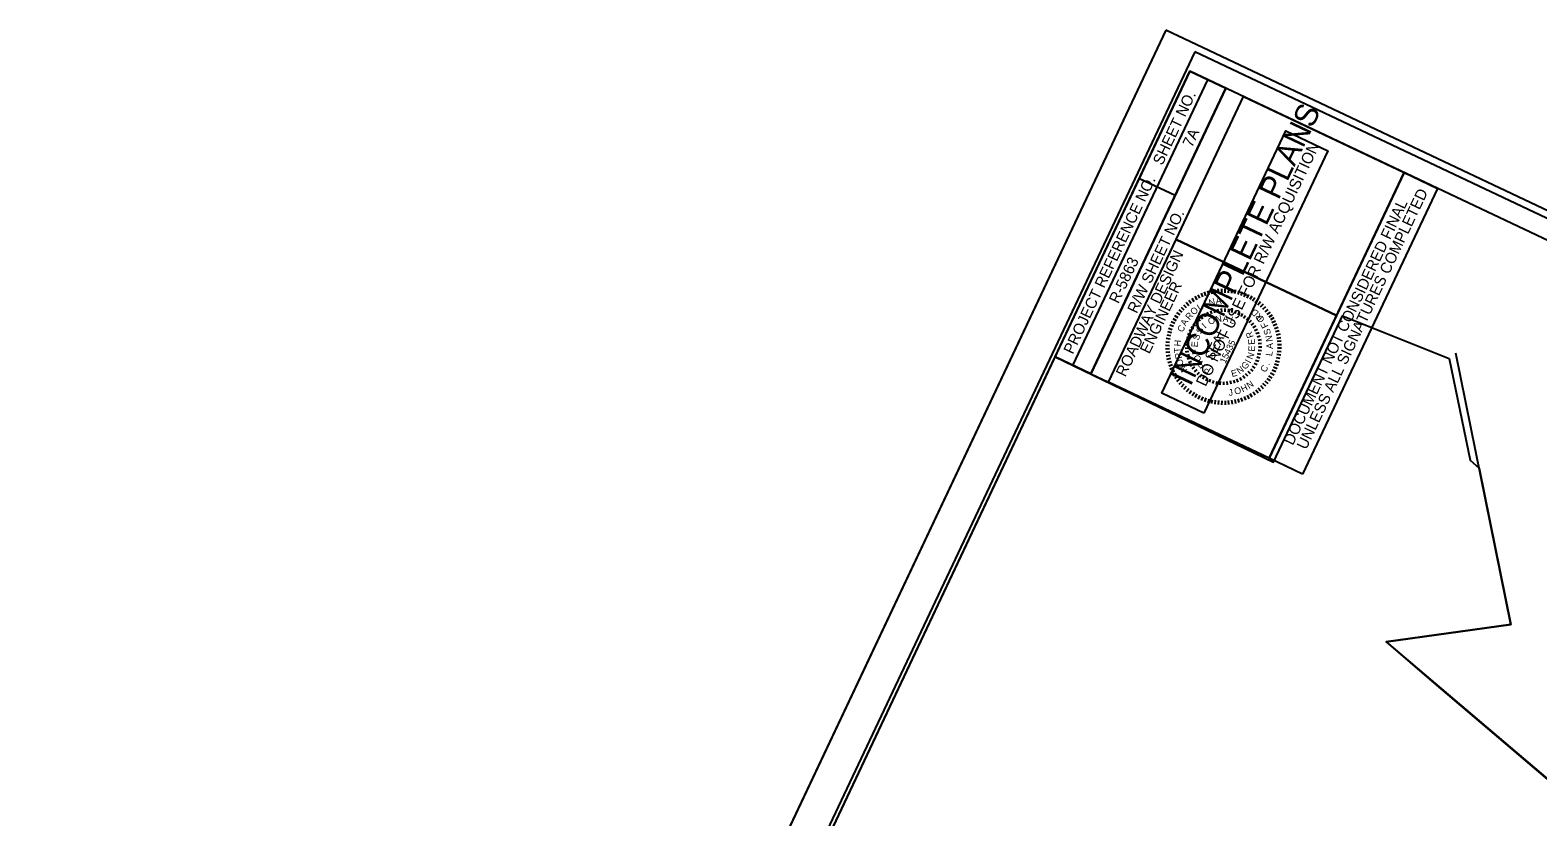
# Model space of a CAD drawing. Extents: x 556536 to 558250, y 505355 to 507347.
# Drawn here: x 556536 to 557491, y 506849 to 507347 of the extents above; entities that cross this region are included whole.
import ezdxf

# ---------------------------------------------------------------- set-up
doc = ezdxf.new("R2010")
doc.units = 0
for name, color, linetype in [('Matchline', 7, 'Continuous'), ('Old_Level_21', 7, 'Continuous'), ('Prop Horizontal Alignment Direction Label', 7, 'Continuous'), ('Prop SS Cut Line', 7, 'Continuous'), ('Prop SS Fill Line', 7, 'Continuous'), ('Prop SS Transition Line', 7, 'Continuous'), ('Scratch_Level_9', 7, 'Continuous'), ('Sheet Clip Boundary CELL', 7, 'Continuous'), ('Sheet Sticker Exception Certification CELL', 7, 'Continuous'), ('Sheet Sticker Incomplete CELL', 7, 'Continuous')]:
    doc.layers.add(name, color=color, linetype=linetype)

msp = doc.modelspace()

# ---------------------------------------------------------------- linework, layer by layer
at = {"layer": 'Matchline'}
for p, q in [((557474.03, 506970.73), (557439.22, 507142.63)), ((557395.12, 506959.79), (557474.03, 506970.73)), ((557395.12, 506959.79), (557889.73, 506539.36))]:
    msp.add_line(p, q, dxfattribs=at)
at = {"layer": 'Old_Level_21'}
for p, q in [((557286.26, 507182.99), (557286.65, 507180.52)), ((557288.46, 507183.27), (557288.7, 507180.78)), ((557290.68, 507183.42), (557290.76, 507180.91)), ((557292.9, 507183.42), (557292.83, 507180.92)), ((557295.11, 507183.3), (557294.9, 507180.81)), ((557297.31, 507183.05), (557296.95, 507180.57)), ((557266.64, 507173.33), (557268.37, 507171.51)), ((557268.3, 507174.81), (557269.91, 507172.9)), ((557270.04, 507176.19), (557271.53, 507174.18)), ((557271.86, 507177.46), (557273.23, 507175.36)), ((557273.75, 507178.62), (557274.99, 507176.44)), ((557275.71, 507179.66), (557276.82, 507177.41)), ((557277.74, 507180.58), (557278.7, 507178.27)), ((557279.81, 507181.37), (557280.63, 507179.01)), ((557281.92, 507182.04), (557282.61, 507179.63)), ((557284.08, 507182.58), (557284.61, 507180.14)), ((557299.5, 507182.65), (557298.98, 507180.21)), ((557301.66, 507182.13), (557301, 507179.72)), ((557303.78, 507181.48), (557302.97, 507179.11)), ((557305.86, 507180.7), (557304.91, 507178.39)), ((557307.89, 507179.8), (557306.8, 507177.55)), ((557309.86, 507178.78), (557308.64, 507176.59)), ((557311.76, 507177.64), (557310.42, 507175.53)), ((557313.6, 507176.39), (557312.12, 507174.36)), ((557315.35, 507175.03), (557313.76, 507173.1)), ((557317.02, 507173.56), (557315.31, 507171.73)), ((557259.86, 507164.6), (557262.05, 507163.38)), ((557261, 507166.5), (557263.11, 507165.15)), ((557262.25, 507168.33), (557264.28, 507166.86)), ((557263.61, 507170.09), (557265.55, 507168.5)), ((557265.08, 507171.76), (557266.91, 507170.05)), ((557275.7, 507164.65), (557277.1, 507163.1)), ((557277.51, 507166.13), (557278.75, 507164.46)), ((557279.45, 507167.44), (557280.53, 507165.65)), ((557281.51, 507168.55), (557282.42, 507166.66)), ((557283.67, 507169.45), (557284.39, 507167.49)), ((557285.91, 507170.14), (557286.43, 507168.12)), ((557288.2, 507170.62), (557288.53, 507168.56)), ((557290.52, 507170.87), (557290.65, 507168.78)), ((557292.87, 507170.89), (557292.79, 507168.81)), ((557295.2, 507170.69), (557294.91, 507168.62)), ((557297.5, 507170.27), (557297.02, 507168.23)), ((557299.75, 507169.62), (557299.07, 507167.65)), ((557301.93, 507168.76), (557301.07, 507166.86)), ((557304.01, 507167.7), (557302.97, 507165.89)), ((557304.71, 507164.77), (557305.92, 507166.48)), ((557307.82, 507164.99), (557306.46, 507163.41)), ((557318.6, 507172), (557316.78, 507170.28)), ((557320.07, 507170.34), (557318.16, 507168.73)), ((557321.45, 507168.61), (557319.44, 507167.11)), ((557322.72, 507166.78), (557320.62, 507165.41)), ((557323.88, 507164.89), (557321.7, 507163.65)), ((557255.99, 507154.24), (557258.44, 507153.72)), ((557256.51, 507156.4), (557258.92, 507155.73)), ((557257.16, 507158.52), (557259.53, 507157.71)), ((557257.94, 507160.6), (557260.25, 507159.65)), ((557258.84, 507162.63), (557261.1, 507161.54)), ((557269.22, 507155.04), (557271.17, 507154.32)), ((557270.13, 507157.19), (557272.01, 507156.29)), ((557272.01, 507156.29), (557270.13, 507157.19)), ((557271.25, 507159.25), (557273.03, 507158.17)), ((557272.55, 507161.19), (557274.23, 507159.94)), ((557274.04, 507162.99), (557275.59, 507161.59)), ((557309.51, 507163.37), (557308, 507161.93)), ((557311.04, 507161.6), (557309.39, 507160.32)), ((557312.39, 507159.69), (557310.63, 507158.57)), ((557313.55, 507157.65), (557311.69, 507156.71)), ((557314.5, 507155.52), (557312.56, 507154.76)), ((557324.92, 507162.93), (557322.67, 507161.82)), ((557325.84, 507160.91), (557323.53, 507159.94)), ((557326.63, 507158.83), (557324.27, 507158.01)), ((557327.3, 507156.72), (557324.9, 507156.04)), ((557327.85, 507154.56), (557325.4, 507154.03)), ((557255.22, 507147.63), (557257.72, 507147.57)), ((557255.22, 507145.41), (557257.73, 507145.5)), ((557255.34, 507149.85), (557257.84, 507149.64)), ((557255.59, 507152.05), (557258.08, 507151.69)), ((557267.75, 507145.85), (557269.83, 507145.92)), ((557267.78, 507148.19), (557269.86, 507148.06)), ((557268.03, 507150.52), (557270.1, 507150.18)), ((557268.52, 507152.81), (557270.54, 507152.28)), ((557315.25, 507153.3), (557313.24, 507152.73)), ((557315.78, 507151.02), (557313.73, 507150.65)), ((557316.09, 507148.7), (557314.01, 507148.53)), ((557316.17, 507146.36), (557314.08, 507146.39)), ((557328.26, 507152.38), (557325.78, 507152)), ((557328.54, 507150.18), (557326.04, 507149.94)), ((557328.68, 507147.97), (557326.17, 507147.88)), ((557328.69, 507145.75), (557326.18, 507145.81)), ((557255.37, 507143.2), (557257.86, 507143.44)), ((557255.65, 507140.99), (557258.12, 507141.38)), ((557256.06, 507138.82), (557258.5, 507139.35)), ((557256.6, 507136.66), (557259.01, 507137.34)), ((557257.27, 507134.54), (557259.63, 507135.37)), ((557267.94, 507143.52), (557270.01, 507143.79)), ((557268.36, 507141.21), (557270.39, 507141.68)), ((557269, 507138.96), (557270.98, 507139.63)), ((557269.85, 507136.78), (557271.75, 507137.64)), ((557270.91, 507134.69), (557272.72, 507135.73)), ((557313.24, 507135.14), (557311.41, 507136.14)), ((557314.26, 507137.25), (557312.34, 507138.07)), ((557315.06, 507139.45), (557313.07, 507140.07)), ((557315.65, 507141.71), (557313.61, 507142.14)), ((557316.02, 507144.02), (557313.95, 507144.25)), ((557326.74, 507134.86), (557324.37, 507135.67)), ((557327.4, 507136.98), (557324.98, 507137.64)), ((557327.92, 507139.14), (557325.47, 507139.66)), ((557328.31, 507141.33), (557325.83, 507141.69)), ((557328.57, 507143.53), (557326.07, 507143.74)), ((557258.06, 507132.47), (557260.37, 507133.44)), ((557258.99, 507130.45), (557261.23, 507131.56)), ((557260.02, 507128.49), (557262.2, 507129.73)), ((557261.18, 507126.6), (557263.28, 507127.96)), ((557262.45, 507124.77), (557264.46, 507126.27)), ((557272.16, 507132.72), (557273.87, 507133.92)), ((557273.61, 507130.87), (557275.19, 507132.24)), ((557275.22, 507129.18), (557276.66, 507130.69)), ((557276.99, 507127.65), (557278.28, 507129.29)), ((557278.89, 507126.29), (557280.02, 507128.05)), ((557280.92, 507125.12), (557281.87, 507126.98)), ((557283.06, 507124.16), (557283.82, 507126.1)), ((557299.12, 507123.56), (557298.51, 507125.55)), ((557301.32, 507124.35), (557300.51, 507126.28)), ((557303.43, 507125.36), (557302.44, 507127.2)), ((557305.44, 507126.57), (557304.27, 507128.31)), ((557307.32, 507127.97), (557305.99, 507129.58)), ((557309.05, 507129.54), (557307.58, 507131.02)), ((557309.01, 507132.59), (557310.62, 507131.25)), ((557312.03, 507133.14), (557310.3, 507134.31)), ((557321.65, 507125.04), (557319.63, 507126.52)), ((557322.9, 507126.88), (557320.79, 507128.23)), ((557324.04, 507128.78), (557321.85, 507130)), ((557325.06, 507130.75), (557322.81, 507131.84)), ((557325.97, 507132.78), (557323.65, 507133.73)), ((557263.83, 507123.04), (557265.74, 507124.65)), ((557265.31, 507121.38), (557267.13, 507123.1)), ((557266.88, 507119.82), (557268.59, 507121.65)), ((557268.55, 507118.35), (557270.15, 507120.28)), ((557270.31, 507116.99), (557271.78, 507119.01)), ((557272.14, 507115.74), (557273.49, 507117.85)), ((557274.04, 507114.6), (557275.26, 507116.79)), ((557285.27, 507123.41), (557285.85, 507125.41)), ((557287.55, 507122.87), (557287.93, 507124.92)), ((557289.87, 507122.56), (557290.05, 507124.64)), ((557292.21, 507122.47), (557292.18, 507124.56)), ((557294.54, 507122.61), (557294.32, 507124.68)), ((557296.86, 507122.97), (557296.44, 507125.02)), ((557308.19, 507113.72), (557307.08, 507115.97)), ((557310.15, 507114.76), (557308.91, 507116.94)), ((557312.04, 507115.92), (557310.68, 507118.02)), ((557313.87, 507117.19), (557312.37, 507119.2)), ((557315.61, 507118.57), (557313.99, 507120.48)), ((557317.26, 507120.05), (557315.54, 507121.86)), ((557318.83, 507121.62), (557316.99, 507123.33)), ((557320.29, 507123.29), (557318.36, 507124.88)), ((557276.01, 507113.58), (557277.1, 507115.83)), ((557278.04, 507112.67), (557278.99, 507114.99)), ((557280.12, 507111.9), (557280.93, 507114.27)), ((557282.24, 507111.25), (557282.91, 507113.66)), ((557284.4, 507110.72), (557284.92, 507113.17)), ((557286.59, 507110.33), (557286.96, 507112.81)), ((557288.79, 507110.08), (557289.01, 507112.57)), ((557291.01, 507109.96), (557291.07, 507112.46)), ((557293.23, 507109.96), (557293.14, 507112.47)), ((557295.45, 507110.11), (557295.2, 507112.6)), ((557297.65, 507110.38), (557297.26, 507112.86)), ((557299.83, 507110.79), (557299.29, 507113.24)), ((557301.98, 507111.34), (557301.3, 507113.75)), ((557304.1, 507112.01), (557303.27, 507114.37)), ((557306.17, 507112.8), (557305.2, 507115.11))]:
    msp.add_line(p, q, dxfattribs=at)
at = {"layer": 'Prop Horizontal Alignment Direction Label'}
msp.add_lwpolyline([(557255.37, 507347.15), (556535.75, 505824.65), (557530.26, 505354.59), (558249.88, 506877.09)], close=True, dxfattribs=at)
at = {"layer": 'Prop SS Cut Line'}
for p, q in [((557196.57, 507134.87), (557282.05, 507315.74)), ((557207.87, 507129.53), (557293.36, 507310.39)), ((557207.87, 507129.53), (557293.36, 507310.39)), ((557238.7, 507253.27), (557261.31, 507242.59)), ((557261.92, 507214.64), (557363.59, 507166.59)), ((557207.87, 507129.53), (557219.17, 507124.19))]:
    msp.add_line(p, q, dxfattribs=at)
for points in [[(557270.71, 507321.1), (556629.72, 505964.95), (557579.02, 505516.26), (558220.01, 506872.41)], [(557185.22, 507140.23), (557270.71, 507321.1), (557293.36, 507310.39), (557207.87, 507129.53)], [(557261.92, 507214.64), (557304.66, 507305.05), (557406.37, 507256.98), (557363.64, 507166.57)], [(557219.17, 507124.19), (557261.92, 507214.64), (557363.64, 507166.57), (557320.88, 507076.11)]]:
    msp.add_lwpolyline(points, close=True, dxfattribs=at)
at = {"layer": 'Prop SS Fill Line'}
msp.add_lwpolyline([(557273.74, 507333.49), (556561.61, 505826.81), (557515.52, 505375.94), (558227.66, 506882.62)], close=True, dxfattribs=at)
at = {"layer": 'Scratch_Level_9'}
msp.add_line((557255.37, 507347.15), (556535.75, 505824.65), dxfattribs=at)
at = {"layer": 'Sheet Clip Boundary CELL'}
msp.add_lwpolyline([(557803.27, 506254.64), (557635.29, 505993.61), (557687.24, 505840.99), (557643.42, 505687.13), (557512.37, 505750.31), (557008.7, 505860.07), (556630.15, 505965.86), (557185.22, 507140.23), (557323.61, 507073.55), (557367.3, 507166.35), (557435.08, 507139.34), (557448.32, 507074.91), (557453.98, 507069.78), (557474.03, 506970.73), (557395.12, 506959.79), (557425.46, 506933.59), (557889.73, 506539.36), (557951.72, 506501.53), (557971.08, 506460.75)], close=True, dxfattribs=at)
at = {"layer": 'Sheet Sticker Exception Certification CELL'}
for p, q in [((557320.88, 507076.11), (557406.36, 507256.97)), ((557406.37, 507256.96), (557427.62, 507246.92)), ((557427.61, 507246.93), (557342.13, 507066.07)), ((557342.13, 507066.07), (557320.88, 507076.11))]:
    msp.add_line(p, q, dxfattribs=at)
at = {"layer": 'Sheet Sticker Incomplete CELL'}
msp.add_lwpolyline([(557279.52, 507104.69), (557252.96, 507117.24), (557331.48, 507283.37), (557358.04, 507270.82)], close=True, dxfattribs=at)

# ---------------------------------------------------------------- texts
at = {"layer": 'Old_Level_21'}
for s, height, rotation, p in [('L', 4.17, 33.45349, (557276.88, 507169.4)), ('I', 4.17, 23.87802, (557280.52, 507171.38)), ('N', 4.17, 14.58355, (557283.2, 507172.41)), ('A', 4.17, 4.81602, (557287.17, 507173.56)), ('R', 4.17, 49.64658, (557270.53, 507163.26)), ('O', 4.17, 46.58977, (557273.37, 507166.38)), ('O', 4.17, 26.05831, (557283.32, 507160.3)), ('N', 4.17, 10.76207, (557287.23, 507161.99)), ('A', 4.17, 355.46582, (557291.3, 507162.57)), ('L', 4.17, 340.16957, (557295.61, 507161.99)), (' RD', 4.171, 133.97135, (557318.56, 507164.26)), ('O ', 4.171, 125.29859, (557318.32, 507163.71)), ('C', 4.17, 61.65589, (557266.01, 507155.47)), ('A', 4.17, 61.65589, (557268.06, 507159.54)), ('S', 4.17, 71.94705, (557276.17, 507150.47)), ('S', 4.17, 56.6508, (557277.66, 507154.37)), ('I', 4.17, 41.35456, (557280.4, 507157.98)), ('SEAL', 6.262, 64.29893, (557285.39, 507137.39)), ('R', 4.17, 108.86382, (557311.11, 507152.98)), ('F', 4.17, 116.50598, (557320.54, 507159.62)), ('S', 4.17, 107.62335, (557322.22, 507154.96)), ('T', 4.17, 94.79853, (557265, 507143.01)), ('H', 4.17, 85.36658, (557264.82, 507146.83)), ('E', 4.17, 87.2433, (557275.76, 507146.32)), ('F', 4.17, 102.53954, (557276.44, 507142.28)), ('15435', 4.171, 64.29893, (557293.12, 507135.76)), ('E', 4.17, 95.09273, (557312.01, 507148.13)), ('E', 4.17, 85.10685, (557311.76, 507143.5)), ('N', 4.17, 98.74072, (557323.13, 507150.19)), ('A', 4.17, 89.91811, (557323.3, 507145.3)), ('R', 4.17, 102.95949, (557265.89, 507139.48)), ('O', 4.17, 116.01622, (557267.11, 507135.53)), ('O', 4.17, 117.83579, (557278.27, 507138.33)), ('R', 4.17, 133.13203, (557280.93, 507135.21)), ('G', 4.17, 43.99032, (557305.59, 507131.95)), ('I', 4.17, 62.08512, (557308.95, 507135.85)), ('N', 4.17, 69.71478, (557310.3, 507138.34)), ('L', 4.17, 80.91554, (557322.72, 507140.57)), ('.', 4.17, 68.13123, (557320.93, 507134.7)), ('N', 4.17, 117.97565, (557269.25, 507131.85)), ('P', 4.17, 148.42828, (557284.38, 507132.85)), ('E', 4.17, 14.36902, (557297.41, 507127.47)), ('N', 4.17, 35.22409, (557302.06, 507129.12)), ('C', 4.17, 60.38888, (557318.58, 507130.08)), ('J', 4.17, 8.23394, (557295.43, 507115.51)), ('O', 4.17, 16.30576, (557299.46, 507116.22)), ('H', 4.17, 24.9485, (557304.1, 507117.76)), ('N', 4.17, 33.62109, (557308.24, 507119.87))]:
    msp.add_text(s, height=height, rotation=rotation, dxfattribs=at).set_placement(p)
at = {"layer": 'Prop SS Cut Line'}
for s, p in [('SHEET NO.', (557253.2, 507261.12)), ('PROJECT REFERENCE NO.', (557196.53, 507141.46)), ('R/W SHEET NO.', (557237, 507167.29)), ('ROADWAY DESIGN', (557229.75, 507127.14)), ('ENGINEER', (557244.98, 507141.71))]:
    msp.add_text(s, height=7, rotation=64.7021, dxfattribs=at).set_placement(p)
at = {"layer": 'Prop SS Transition Line'}
for s, p in [('7A', (557272.02, 507272.39)), ('R-5863', (557225.36, 507173.55))]:
    msp.add_text(s, height=7, rotation=64.7021, dxfattribs=at).set_placement(p)
at = {"layer": 'Sheet Sticker Exception Certification CELL'}
for s, p in [('UNLESS ALL SIGNATURES COMPLETED', (557344.39, 507081.06)), ('DOCUMENT NOT CONSIDERED FINAL', (557335.96, 507083.8))]:
    msp.add_text(s, height=7, rotation=64.7021, dxfattribs=at).set_placement(p)
at = {"layer": 'Sheet Sticker Incomplete CELL'}
for s, height, p in [('INCOMPLETE PLANS', 14.4, (557271.07, 507121.08)), ('DO NOT USE FOR R/W ACQUISITION', 7.2, (557280.66, 507121.04))]:
    msp.add_text(s, height=height, rotation=64.7021, dxfattribs=at).set_placement(p)

doc.saveas('drawing.dxf')
